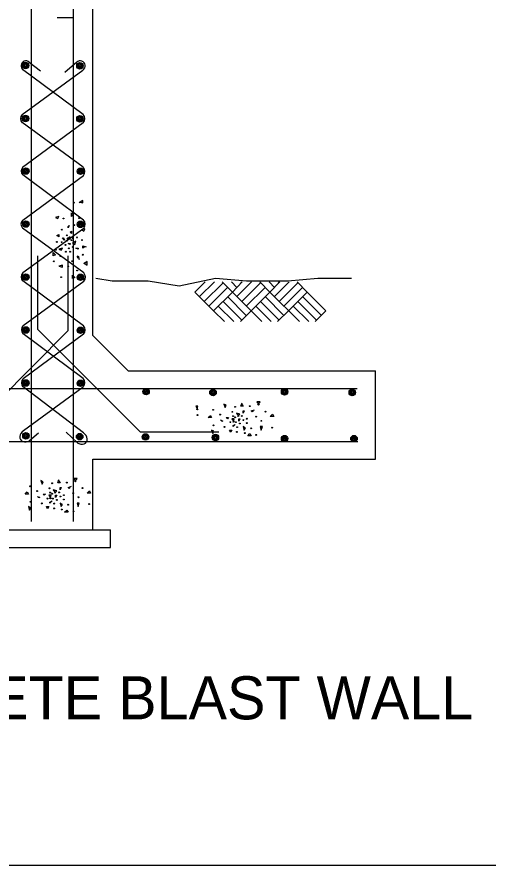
# Model space of a CAD drawing. Extents: x -0.04 to 2.79, y -0.02 to 1.81.
# Drawn here: x 1.4969 to 1.6109, y 0.4885 to 0.6936 of the extents above; entities that cross this region are included whole.
import ezdxf

# ---------------------------------------------------------------- set-up
doc = ezdxf.new("R2010")
doc.units = 0
doc.layers.add('Level 1', color=7, linetype='Continuous')
doc.layers.add('Level 2', color=7, linetype='Continuous')

msp = doc.modelspace()

# ---------------------------------------------------------------- linework, layer by layer
msp.add_line((0.11656, 0.48847), (2.51784, 0.48847))
at = {"layer": 'Level 1'}
for p, q in [((1.50043, 0.57154), (1.50043, 0.81118)), ((1.51062, 0.57154), (1.51062, 0.81104)), ((1.51527, 0.61658), (1.51527, 0.81214)), ((1.51055, 0.69341), (1.50659, 0.69341)), ((1.49989, 0.68268), (1.50262, 0.68056)), ((1.51137, 0.68268), (1.5085, 0.68015)), ((1.49818, 0.67003), (1.51287, 0.68076)), ((1.51294, 0.67003), (1.49825, 0.6809)), ((1.51294, 0.65725), (1.49818, 0.66805)), ((1.49825, 0.65725), (1.51294, 0.66805)), ((1.51301, 0.64447), (1.49832, 0.65541)), ((1.49832, 0.64447), (1.51301, 0.65527)), ((1.51308, 0.63169), (1.49825, 0.64249)), ((1.49832, 0.63176), (1.51308, 0.64249)), ((1.50194, 0.61802), (1.50194, 0.63579)), ((1.50932, 0.61775), (1.50932, 0.63579)), ((1.51301, 0.61891), (1.49832, 0.62978)), ((1.49838, 0.61898), (1.51308, 0.62971)), ((1.53994, 0.62704), (1.5424, 0.6295)), ((1.5411, 0.62595), (1.54466, 0.6295)), ((1.5422, 0.62479), (1.54678, 0.6293)), ((1.54336, 0.62362), (1.54787, 0.6282)), ((1.54903, 0.62704), (1.54657, 0.6295)), ((1.55013, 0.6282), (1.54883, 0.6295)), ((1.54903, 0.62704), (1.55142, 0.6295)), ((1.54903, 0.62704), (1.55142, 0.6295)), ((1.55013, 0.62595), (1.55368, 0.6295)), ((1.55129, 0.6293), (1.55108, 0.6295)), ((1.55129, 0.62479), (1.5558, 0.6293)), ((1.55238, 0.62362), (1.55696, 0.6282)), ((1.55805, 0.62704), (1.55566, 0.6295)), ((1.55922, 0.6282), (1.55792, 0.6295)), ((1.55805, 0.62704), (1.56051, 0.6295)), ((1.55805, 0.62704), (1.56051, 0.6295)), ((1.55922, 0.62595), (1.56277, 0.6295)), ((1.56031, 0.6293), (1.56017, 0.6295)), ((1.56031, 0.62479), (1.56489, 0.6293)), ((1.56147, 0.62362), (1.56598, 0.6282)), ((1.56714, 0.62704), (1.56468, 0.6295)), ((1.54445, 0.62253), (1.53994, 0.62704)), ((1.54445, 0.62253), (1.54903, 0.62704)), ((1.55238, 0.62137), (1.54787, 0.62595)), ((1.55354, 0.62253), (1.54903, 0.62704)), ((1.55354, 0.62253), (1.55805, 0.62704)), ((1.56147, 0.62137), (1.55696, 0.62595)), ((1.56523, 0.61993), (1.55805, 0.62704)), ((1.56263, 0.62253), (1.56714, 0.62704)), ((1.57056, 0.62137), (1.56598, 0.62595)), ((1.57166, 0.62253), (1.56714, 0.62704)), ((1.54937, 0.61993), (1.54561, 0.62362)), ((1.55129, 0.62027), (1.54678, 0.62479)), ((1.5584, 0.61993), (1.5547, 0.62362)), ((1.56031, 0.62027), (1.5558, 0.62479)), ((1.56749, 0.61993), (1.56373, 0.62362)), ((1.5694, 0.62027), (1.56489, 0.62479)), ((1.54712, 0.61993), (1.54445, 0.62253)), ((1.55095, 0.61993), (1.55354, 0.62253)), ((1.55614, 0.61993), (1.55354, 0.62253)), ((1.55997, 0.61993), (1.56263, 0.62253)), ((1.56906, 0.61993), (1.57166, 0.62253)), ((1.48478, 0.59321), (1.50932, 0.61775)), ((1.52668, 0.59328), (1.50194, 0.61802)), ((1.51294, 0.60619), (1.49838, 0.61699)), ((1.49838, 0.60613), (1.51301, 0.61693)), ((1.52381, 0.60804), (1.51527, 0.61658)), ((1.52381, 0.60804), (1.58362, 0.60804)), ((1.58362, 0.58665), (1.58362, 0.60804)), ((1.43167, 0.60373), (1.57924, 0.60373)), ((1.51301, 0.593), (1.49838, 0.60414)), ((1.49852, 0.59355), (1.51294, 0.60414)), ((1.49996, 0.59116), (1.50214, 0.593)), ((1.51151, 0.59061), (1.50884, 0.59314)), ((1.52668, 0.59328), (1.54575, 0.59328)), ((1.43181, 0.59095), (1.57938, 0.59095)), ((1.51527, 0.58665), (1.58362, 0.58665)), ((1.51527, 0.56956), (1.51527, 0.58665)), ((1.49175, 0.56956), (1.51957, 0.56956)), ((1.51957, 0.56525), (1.51957, 0.56956)), ((1.49175, 0.56525), (1.51957, 0.56525))]:
    msp.add_line(p, q, dxfattribs=at)
msp.add_lwpolyline([(1.51602, 0.63039), (1.51991, 0.62978), (1.52265, 0.62978), (1.52866, 0.62978), (1.53618, 0.62854), (1.54493, 0.63039), (1.55245, 0.62978), (1.56243, 0.62978), (1.56967, 0.63039), (1.57781, 0.63039)], dxfattribs=at)
for centre, radius in [((1.49898, 0.68186), 0.00079), ((1.49898, 0.68186), 0.000613), ((1.49898, 0.68186), 0.000449), ((1.49898, 0.68186), 0.000227), ((1.51214, 0.68179), 0.00079), ((1.51214, 0.68179), 0.000613), ((1.51214, 0.68179), 0.000449), ((1.51214, 0.68179), 0.000227), ((1.49898, 0.66904), 0.00079), ((1.49898, 0.66904), 0.000613), ((1.49898, 0.66904), 0.000449), ((1.49898, 0.66904), 0.000227), ((1.51214, 0.66897), 0.00079), ((1.51214, 0.66897), 0.000613), ((1.51214, 0.66897), 0.000449), ((1.51214, 0.66897), 0.000227), ((1.49908, 0.65633), 0.00079), ((1.49908, 0.65633), 0.000613), ((1.49908, 0.65633), 0.000449), ((1.49908, 0.65633), 0.000227), ((1.51224, 0.65626), 0.00079), ((1.51224, 0.65626), 0.000613), ((1.51224, 0.65626), 0.000449), ((1.51224, 0.65626), 0.000227), ((1.49908, 0.64351), 0.00079), ((1.49908, 0.64351), 0.000613), ((1.51224, 0.64344), 0.00079), ((1.49908, 0.64351), 0.000449), ((1.49908, 0.64351), 0.000227), ((1.51224, 0.64344), 0.000613), ((1.51224, 0.64344), 0.000449), ((1.51224, 0.64344), 0.000227), ((1.49908, 0.63069), 0.00079), ((1.49908, 0.63069), 0.000613), ((1.49908, 0.63069), 0.000449), ((1.49908, 0.63069), 0.000227), ((1.51224, 0.63063), 0.00079), ((1.51224, 0.63063), 0.000613), ((1.51224, 0.63063), 0.000449), ((1.51224, 0.63063), 0.000227), ((1.49908, 0.61788), 0.00079), ((1.49908, 0.61788), 0.000613), ((1.49908, 0.61788), 0.000449), ((1.49908, 0.61788), 0.000227), ((1.51224, 0.61781), 0.00079), ((1.51224, 0.61781), 0.000613), ((1.51224, 0.61781), 0.000449), ((1.51224, 0.61781), 0.000227), ((1.49908, 0.60506), 0.00079), ((1.49908, 0.60506), 0.000613), ((1.49908, 0.60506), 0.000449), ((1.49908, 0.60506), 0.000227), ((1.51224, 0.60499), 0.00079), ((1.51224, 0.60499), 0.000613), ((1.51224, 0.60499), 0.000449), ((1.51224, 0.60499), 0.000227), ((1.52813, 0.60298), 0.00079), ((1.52813, 0.60298), 0.000613), ((1.52813, 0.60298), 0.000449), ((1.52813, 0.60298), 0.000227), ((1.54433, 0.60277), 0.00079), ((1.54433, 0.60277), 0.000613), ((1.54433, 0.60277), 0.000449), ((1.56166, 0.60291), 0.00079), ((1.56166, 0.60291), 0.000613), ((1.56166, 0.60291), 0.000449), ((1.56166, 0.60291), 0.000227), ((1.57803, 0.60277), 0.00079), ((1.57803, 0.60277), 0.000613), ((1.57803, 0.60277), 0.000449), ((1.54433, 0.60277), 0.000227), ((1.57803, 0.60277), 0.000227), ((1.49908, 0.59228), 0.00079), ((1.49908, 0.59228), 0.000613), ((1.51207, 0.59208), 0.00079), ((1.49908, 0.59228), 0.000449), ((1.49908, 0.59228), 0.000227), ((1.51207, 0.59208), 0.000613), ((1.51207, 0.59208), 0.000449), ((1.51207, 0.59208), 0.000227), ((1.528, 0.59201), 0.00079), ((1.528, 0.59201), 0.000613), ((1.528, 0.59201), 0.000449), ((1.528, 0.59201), 0.000227), ((1.54491, 0.59187), 0.00079), ((1.54491, 0.59187), 0.000613), ((1.54491, 0.59187), 0.000449), ((1.54491, 0.59187), 0.000227), ((1.56166, 0.5916), 0.00079), ((1.56166, 0.5916), 0.000613), ((1.56166, 0.5916), 0.000449), ((1.56166, 0.5916), 0.000227), ((1.57844, 0.5916), 0.00079), ((1.57844, 0.5916), 0.000613), ((1.57844, 0.5916), 0.000449), ((1.57844, 0.5916), 0.000227)]:
    msp.add_circle(centre, radius, dxfattribs=at)
for centre, radius, start, end in [((1.49909, 0.68176), 0.00122, 48.9589, 234.7267), ((1.51217, 0.68176), 0.00122, 305.2733, 131.0411), ((1.49921, 0.66899), 0.00144, 135.5241, 222.5004), ((1.51188, 0.66899), 0.00144, 317.4996, 44.4759), ((1.49938, 0.65635), 0.00144, 135.5241, 222.5004), ((1.51191, 0.65621), 0.00144, 317.4996, 44.4759), ((1.49931, 0.64346), 0.00144, 135.5241, 222.5004), ((1.51198, 0.64346), 0.00144, 317.4996, 44.4759), ((1.49934, 0.63071), 0.00144, 135.5241, 222.5004), ((1.51202, 0.63068), 0.00144, 317.4996, 44.4759), ((1.49941, 0.61793), 0.00144, 135.5241, 222.5004), ((1.51195, 0.61786), 0.00144, 317.4996, 44.4759), ((1.49941, 0.60508), 0.00144, 135.5241, 222.5004), ((1.51188, 0.60515), 0.00144, 317.4996, 44.4759)]:
    msp.add_arc(centre, radius, start, end, dxfattribs=at)
for centre, major_axis, start_param, end_param in [((1.49927, 0.59234), (-0.00152, -0.00097), 4.712389, 7.853982), ((1.51222, 0.59179), (-0.00152, 0.00097), 1.570796, 4.712389)]:
    msp.add_ellipse(centre, major_axis=major_axis, ratio=0.775528, start_param=start_param, end_param=end_param, dxfattribs=at)
at = {"layer": 'Level 2'}
for points in [[(1.51199, 0.64891), (1.51281, 0.64864), (1.51281, 0.64919), (1.51199, 0.64864)], [(1.51062, 0.64563), (1.51007, 0.64536), (1.51007, 0.64618), (1.51062, 0.64563)], [(1.50624, 0.64509), (1.50679, 0.64481), (1.50706, 0.64536), (1.50624, 0.64509)], [(1.50925, 0.64263), (1.50925, 0.6429), (1.50952, 0.64317), (1.50925, 0.64263)], [(1.51253, 0.64208), (1.51308, 0.6418), (1.51335, 0.64235), (1.51253, 0.64208)], [(1.50652, 0.64071), (1.50706, 0.64098), (1.50706, 0.64044)], [(1.50706, 0.64044), (1.50652, 0.64071)], [(1.50843, 0.63962), (1.50788, 0.64016), (1.50816, 0.64016), (1.50843, 0.63962)], [(1.50898, 0.64016), (1.5098, 0.63989), (1.5098, 0.64044), (1.50898, 0.63989)], [(1.51007, 0.64126), (1.5098, 0.64153), (1.51007, 0.6418), (1.51007, 0.64126)], [(1.5098, 0.63852), (1.50925, 0.6388), (1.5098, 0.6388), (1.5098, 0.63852)], [(1.51035, 0.63907), (1.51089, 0.63852), (1.51117, 0.63934), (1.51035, 0.6388)], [(1.51335, 0.63798), (1.51281, 0.6377), (1.51281, 0.63825), (1.51363, 0.63798)], [(1.50624, 0.63606), (1.5057, 0.63579), (1.5057, 0.63661), (1.50624, 0.63606)], [(1.50706, 0.63743), (1.50761, 0.63716), (1.50788, 0.6377), (1.50706, 0.63743)], [(1.51171, 0.63743), (1.51117, 0.6377), (1.51171, 0.6377), (1.51171, 0.63743)], [(1.51171, 0.63524), (1.51144, 0.63552), (1.51171, 0.63579), (1.51199, 0.63497)], [(1.51308, 0.63415), (1.5139, 0.6336), (1.5139, 0.63442), (1.51308, 0.63388)], [(1.50706, 0.63333), (1.50788, 0.63306), (1.50788, 0.6336), (1.50706, 0.63333)], [(1.51089, 0.6306), (1.51035, 0.63032), (1.51035, 0.63114), (1.51089, 0.6306)], [(1.54042, 0.59861), (1.54069, 0.59943), (1.54015, 0.59943), (1.54069, 0.59861)], [(1.54725, 0.59915), (1.54753, 0.5997), (1.54698, 0.59997), (1.54725, 0.59915)], [(1.55136, 0.59997), (1.55163, 0.59943), (1.55108, 0.59943), (1.55136, 0.60025)], [(1.55518, 0.5997), (1.55573, 0.60052), (1.55491, 0.60052), (1.55546, 0.5997)], [(1.5437, 0.59724), (1.54397, 0.59669), (1.54315, 0.59669), (1.5437, 0.59724)], [(1.55026, 0.59697), (1.55081, 0.59751), (1.54999, 0.59779), (1.55054, 0.59697)], [(1.5519, 0.59833), (1.55163, 0.59779), (1.55163, 0.59833), (1.5519, 0.59833)], [(1.55409, 0.59833), (1.55382, 0.59806), (1.55354, 0.59833), (1.55436, 0.59861)], [(1.55874, 0.59751), (1.55901, 0.59697), (1.55819, 0.59697), (1.55874, 0.59751)], [(1.54671, 0.59587), (1.54643, 0.59587), (1.54616, 0.59615), (1.54671, 0.59587)], [(1.54807, 0.59669), (1.5478, 0.59642), (1.54753, 0.59669), (1.54807, 0.59669)], [(1.54917, 0.5956), (1.54944, 0.59642), (1.5489, 0.59642), (1.54944, 0.5956)], [(1.54972, 0.59505), (1.54917, 0.59451), (1.54917, 0.59478), (1.54972, 0.59505)], [(1.55081, 0.59642), (1.55054, 0.59587), (1.55054, 0.59642), (1.55081, 0.59642)], [(1.54425, 0.59287), (1.54452, 0.59341), (1.54397, 0.59369), (1.54425, 0.59287)], [(1.54862, 0.59314), (1.54835, 0.59369), (1.5489, 0.59369)], [(1.5489, 0.59369), (1.54862, 0.59314)], [(1.5519, 0.59369), (1.55218, 0.59423), (1.55163, 0.59451), (1.5519, 0.59369)], [(1.55327, 0.59287), (1.55354, 0.59232), (1.55272, 0.59232), (1.55327, 0.59287)], [(1.556, 0.59369), (1.55628, 0.59451), (1.55573, 0.59451), (1.556, 0.59369)], [(1.50296, 0.58063), (1.50324, 0.58118), (1.50269, 0.58145), (1.50296, 0.58063)], [(1.50706, 0.58145), (1.50734, 0.5809), (1.50679, 0.5809), (1.50706, 0.58172)], [(1.51089, 0.58118), (1.51144, 0.582), (1.51062, 0.582), (1.51117, 0.58118)], [(1.49941, 0.57872), (1.49968, 0.57817), (1.49886, 0.57817), (1.49941, 0.57872)], [(1.50597, 0.57844), (1.50652, 0.57899), (1.5057, 0.57926), (1.50624, 0.57844)], [(1.50761, 0.57981), (1.50734, 0.57926), (1.50734, 0.57981), (1.50761, 0.57981)], [(1.5098, 0.57981), (1.50952, 0.57954), (1.50925, 0.57981), (1.51007, 0.58008)], [(1.51445, 0.57899), (1.51472, 0.57844), (1.5139, 0.57844), (1.51445, 0.57899)], [(1.50242, 0.57735), (1.50214, 0.57735), (1.50187, 0.57762), (1.50242, 0.57735)], [(1.50378, 0.57817), (1.50351, 0.5779), (1.50324, 0.57817), (1.50378, 0.57817)], [(1.50488, 0.57708), (1.50515, 0.5779), (1.5046, 0.5779), (1.50515, 0.57708)], [(1.50542, 0.57653), (1.50488, 0.57598), (1.50488, 0.57626), (1.50542, 0.57653)], [(1.50652, 0.5779), (1.50624, 0.57735), (1.50624, 0.5779), (1.50652, 0.5779)], [(1.49996, 0.57434), (1.50023, 0.57489), (1.49968, 0.57516), (1.49996, 0.57434)], [(1.50433, 0.57462), (1.50406, 0.57516), (1.5046, 0.57516)], [(1.5046, 0.57516), (1.50433, 0.57462)], [(1.50761, 0.57516), (1.50788, 0.57571), (1.50734, 0.57598), (1.50761, 0.57516)], [(1.50898, 0.57434), (1.50925, 0.5738), (1.50843, 0.5738), (1.50898, 0.57434)], [(1.51171, 0.57516), (1.51199, 0.57598), (1.51144, 0.57598), (1.51171, 0.57516)]]:
    msp.add_lwpolyline(points, dxfattribs=at)
for centre in [(1.51064, 0.64868), (1.50816, 0.64486), (1.51192, 0.64493), (1.50779, 0.64215), (1.51076, 0.64327), (1.50894, 0.64078), (1.51038, 0.64012), (1.51143, 0.64028), (1.50657, 0.63917), (1.50772, 0.63912), (1.50861, 0.63846), (1.50894, 0.63945), (1.5101, 0.63961), (1.51043, 0.63796), (1.51264, 0.63963), (1.50629, 0.6373), (1.50872, 0.63681), (1.50944, 0.63763), (1.50977, 0.63681), (1.51281, 0.63609), (1.50585, 0.63449), (1.50744, 0.63576), (1.51026, 0.63454), (1.50926, 0.63328), (1.51148, 0.63228), (1.50761, 0.63067), (1.54967, 0.5993), (1.55321, 0.59946), (1.54061, 0.5973), (1.54437, 0.59858), (1.54603, 0.59741), (1.54901, 0.59809), (1.54918, 0.59704), (1.55134, 0.59708), (1.55476, 0.59692), (1.55702, 0.59813), (1.54444, 0.59482), (1.54852, 0.59559), (1.54969, 0.59676), (1.54985, 0.59559), (1.55083, 0.59526), (1.55167, 0.5961), (1.55249, 0.59643), (1.55249, 0.59538), (1.55602, 0.59592), (1.54714, 0.59444), (1.55013, 0.59323), (1.55018, 0.59438), (1.552, 0.59295), (1.55354, 0.5941), (1.55863, 0.59426), (1.5548, 0.59251), (1.50541, 0.58081), (1.50896, 0.58097), (1.50011, 0.58009), (1.50177, 0.57892), (1.50476, 0.5796), (1.50492, 0.57855), (1.50709, 0.5786), (1.5105, 0.57843), (1.51276, 0.57965), (1.50018, 0.57633), (1.50426, 0.5771), (1.50543, 0.57827), (1.50559, 0.5771), (1.50658, 0.57677), (1.50741, 0.57761), (1.50823, 0.57794), (1.50823, 0.57689), (1.51176, 0.57743), (1.50289, 0.57595), (1.50587, 0.57474), (1.50592, 0.57589), (1.50774, 0.57446), (1.50928, 0.57561), (1.51437, 0.57577), (1.51055, 0.57402)]:
    msp.add_circle(centre, 0.000107, dxfattribs=at)

# ---------------------------------------------------------------- texts
msp.add_text('B15 - CONCRETE BLAST WALL', height=0.0104167).set_placement((1.40219, 0.52371))

doc.saveas('drawing.dxf')
